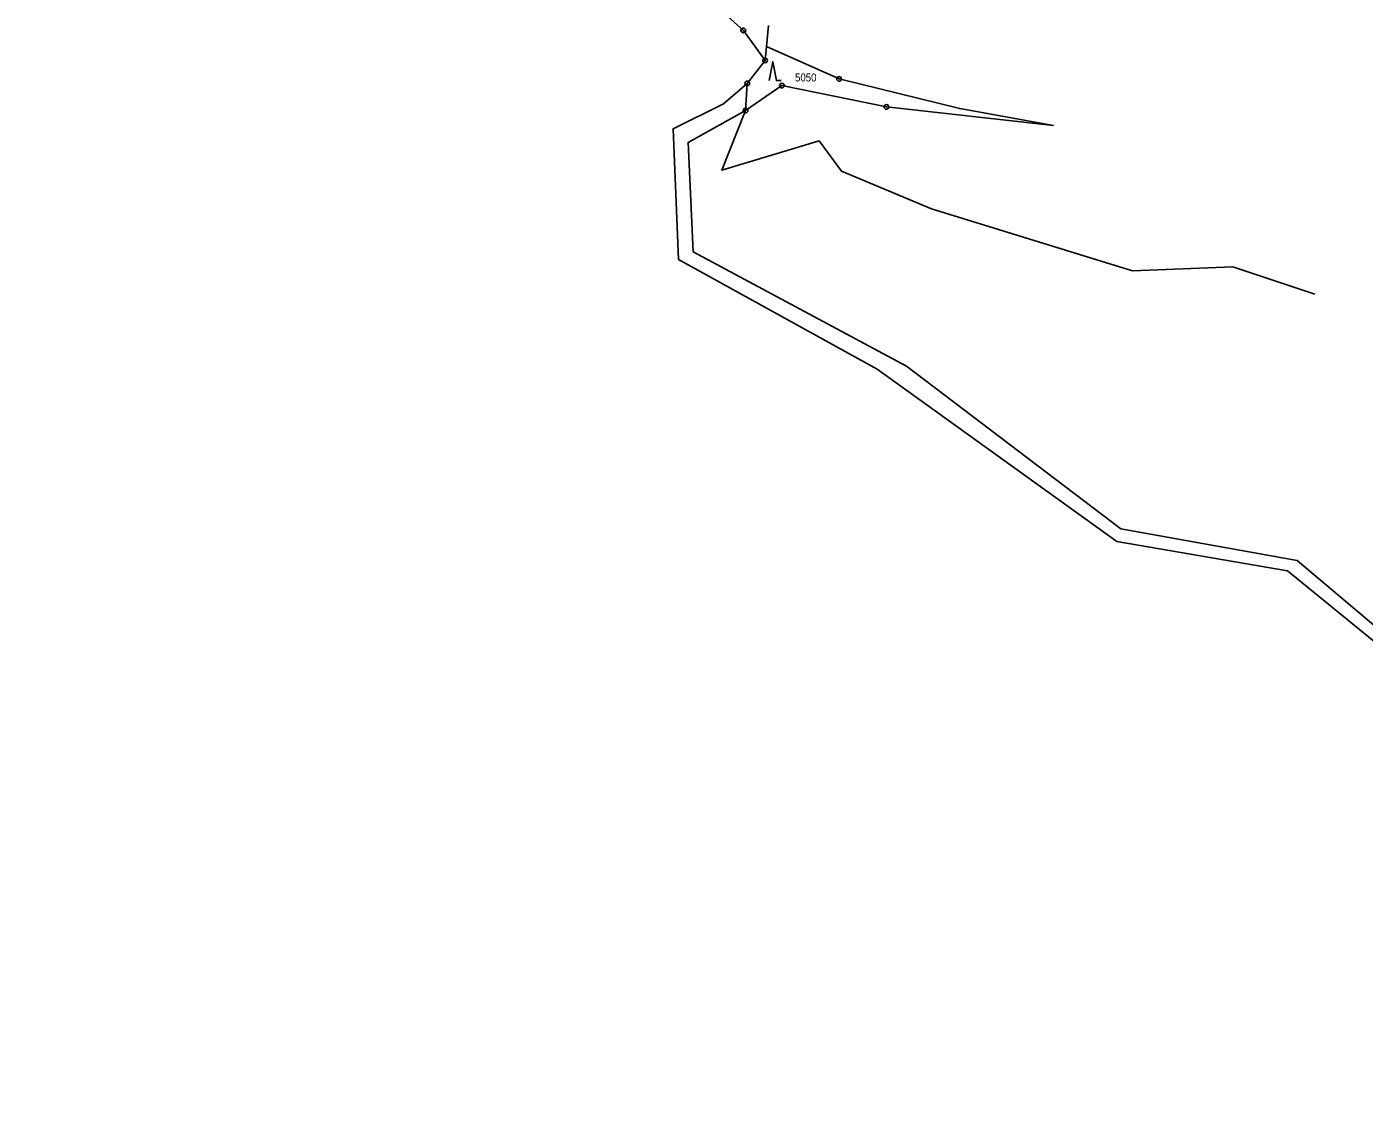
# Model space of a CAD drawing. Extents: x -665688 to -664583, y -1006118 to -1004927.
# Drawn here: x -665688.4 to -665404.3, y -1006117.7 to -1005890.9 of the extents above; entities that cross this region are included whole.
import ezdxf
from ezdxf.enums import TextEntityAlignment as Align

# ---------------------------------------------------------------- set-up
doc = ezdxf.new("R2010")
doc.units = 0
doc.header["$LTSCALE"] = 0.68
for name, color, linetype, lineweight in [('1', 7, 'Continuous', 25), ('24', 7, 'Continuous', 25), ('25', 7, 'Continuous', 25)]:
    doc.layers.add(name, color=color, linetype=linetype, lineweight=lineweight)
doc.layers.add('18', color=7, linetype='Continuous')

msp = doc.modelspace()

# ---------------------------------------------------------------- linework, layer by layer
at = {"layer": '1'}
for points in [[(-665688.38, -1005753.28), (-665680.51, -1005760.89), (-665664.8, -1005765.04), (-665619.09, -1005806.67), (-665598.43, -1005838.79), (-665557.93, -1005872.16), (-665536.17, -1005891.7), (-665531.55, -1005898.07)], [(-665470.32, -1005911.86), (-665490.2, -1005908.29), (-665515.84, -1005902), (-665531.27, -1005895.08), (-665530.86, -1005890.61)], [(-665470.32, -1005911.86), (-665505.77, -1005907.95), (-665527.99, -1005903.4), (-665535.7, -1005908.73), (-665535.33, -1005902.95), (-665531.55, -1005898.07), (-665531.27, -1005895.08)], [(-665535.33, -1005902.95), (-665540.4, -1005907.25), (-665551.08, -1005912.59), (-665549.94, -1005940.38), (-665507.74, -1005963.63), (-665456.82, -1006000.28), (-665420.61, -1006006.49), (-665368.95, -1006048.56), (-665268.26, -1006117.71), (-665241.45, -1006112.83), (-665172.9, -1006090.52), (-665067.23, -1006069.33)], [(-665065.41, -1006065.42), (-665173.46, -1006087.28), (-665243.51, -1006110.42), (-665266.2, -1006114.7), (-665353.84, -1006055.7), (-665393.23, -1006025.64), (-665418.55, -1006004.28), (-665456, -1005997.56), (-665501.54, -1005963.05), (-665546.81, -1005938.76), (-665547.91, -1005915.48), (-665535.7, -1005908.73)], [(-665414.76, -1005947.74), (-665432.21, -1005941.94), (-665453.54, -1005942.78), (-665496.23, -1005929.56), (-665515.32, -1005921.57), (-665520.09, -1005915.17), (-665540.73, -1005921.39), (-665535.7, -1005908.73)]]:
    msp.add_lwpolyline(points, dxfattribs=at)
at = {"layer": '24'}
for centre, radius in [((-665536.17, -1005891.7), 0.5), ((-665536.17, -1005891.7), 0.032), ((-665531.55, -1005898.07), 0.5), ((-665531.55, -1005898.07), 0.032), ((-665535.33, -1005902.95), 0.5), ((-665515.84, -1005902), 0.5), ((-665515.84, -1005902), 0.032), ((-665535.33, -1005902.95), 0.032), ((-665527.99, -1005903.4), 0.5), ((-665527.99, -1005903.4), 0.032), ((-665505.77, -1005907.95), 0.5), ((-665505.77, -1005907.95), 0.032), ((-665535.7, -1005908.73), 0.5), ((-665535.7, -1005908.73), 0.032)]:
    msp.add_circle(centre, radius, dxfattribs=at)
at = {"layer": '25'}
msp.add_lwpolyline([(-665530.66, -1005902.35), (-665529.91, -1005898.35), (-665529.16, -1005902.35), (-665528.16, -1005902.35)], dxfattribs=at)

# ---------------------------------------------------------------- texts
at = {"layer": '18', "width": 0.9}
msp.add_text('5050', height=1.7, dxfattribs=at).set_placement((-665522.9095, -1005902.53), align=Align.CENTER)

doc.saveas('drawing.dxf')
